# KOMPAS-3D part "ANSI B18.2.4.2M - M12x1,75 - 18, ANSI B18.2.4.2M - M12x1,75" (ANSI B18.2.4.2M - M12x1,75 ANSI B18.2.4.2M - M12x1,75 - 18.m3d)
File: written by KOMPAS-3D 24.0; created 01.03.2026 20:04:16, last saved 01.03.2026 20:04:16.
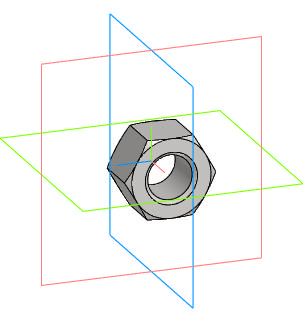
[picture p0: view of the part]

Document properties: Автор: R2D2; Полное имя файла: E:\Работа\Зайцев\GVWR3131M-2W-F-S Задвижка клиновая с выдвижным штоком DN.ru Ду50-200 Ру63\DN80\исходные материалы\ANSI B18.2.4.2M - M12x1,75 ANSI B18.2.4.2M - M12x1,75 - 18.m3d

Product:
- Body: Solid1  | qty 1
- Part/product: ANSI B18.2.4.2M - M12x1,75 - 18  | designation ANSI B18.2.4.2M - M12x1,75
    Комментарий: Типы метрических   шестигранных гаек   2
    additional columns: Сталь, мягкая

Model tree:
1. Solid1  (labels: Solid1)

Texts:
  ANSI B18.2.4.2M - M12x1,75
